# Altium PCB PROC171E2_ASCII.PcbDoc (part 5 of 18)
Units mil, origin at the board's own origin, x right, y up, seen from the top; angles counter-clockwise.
Board outline 7700 x 2300 mil, 6 copper layers (Top Layer, GND 1, SIG 1, SIG 2, GND 2, Bottom Layer), stack 61.062 mil thick; 938 components, 688 nets, 11933 pads, 1723 vias.
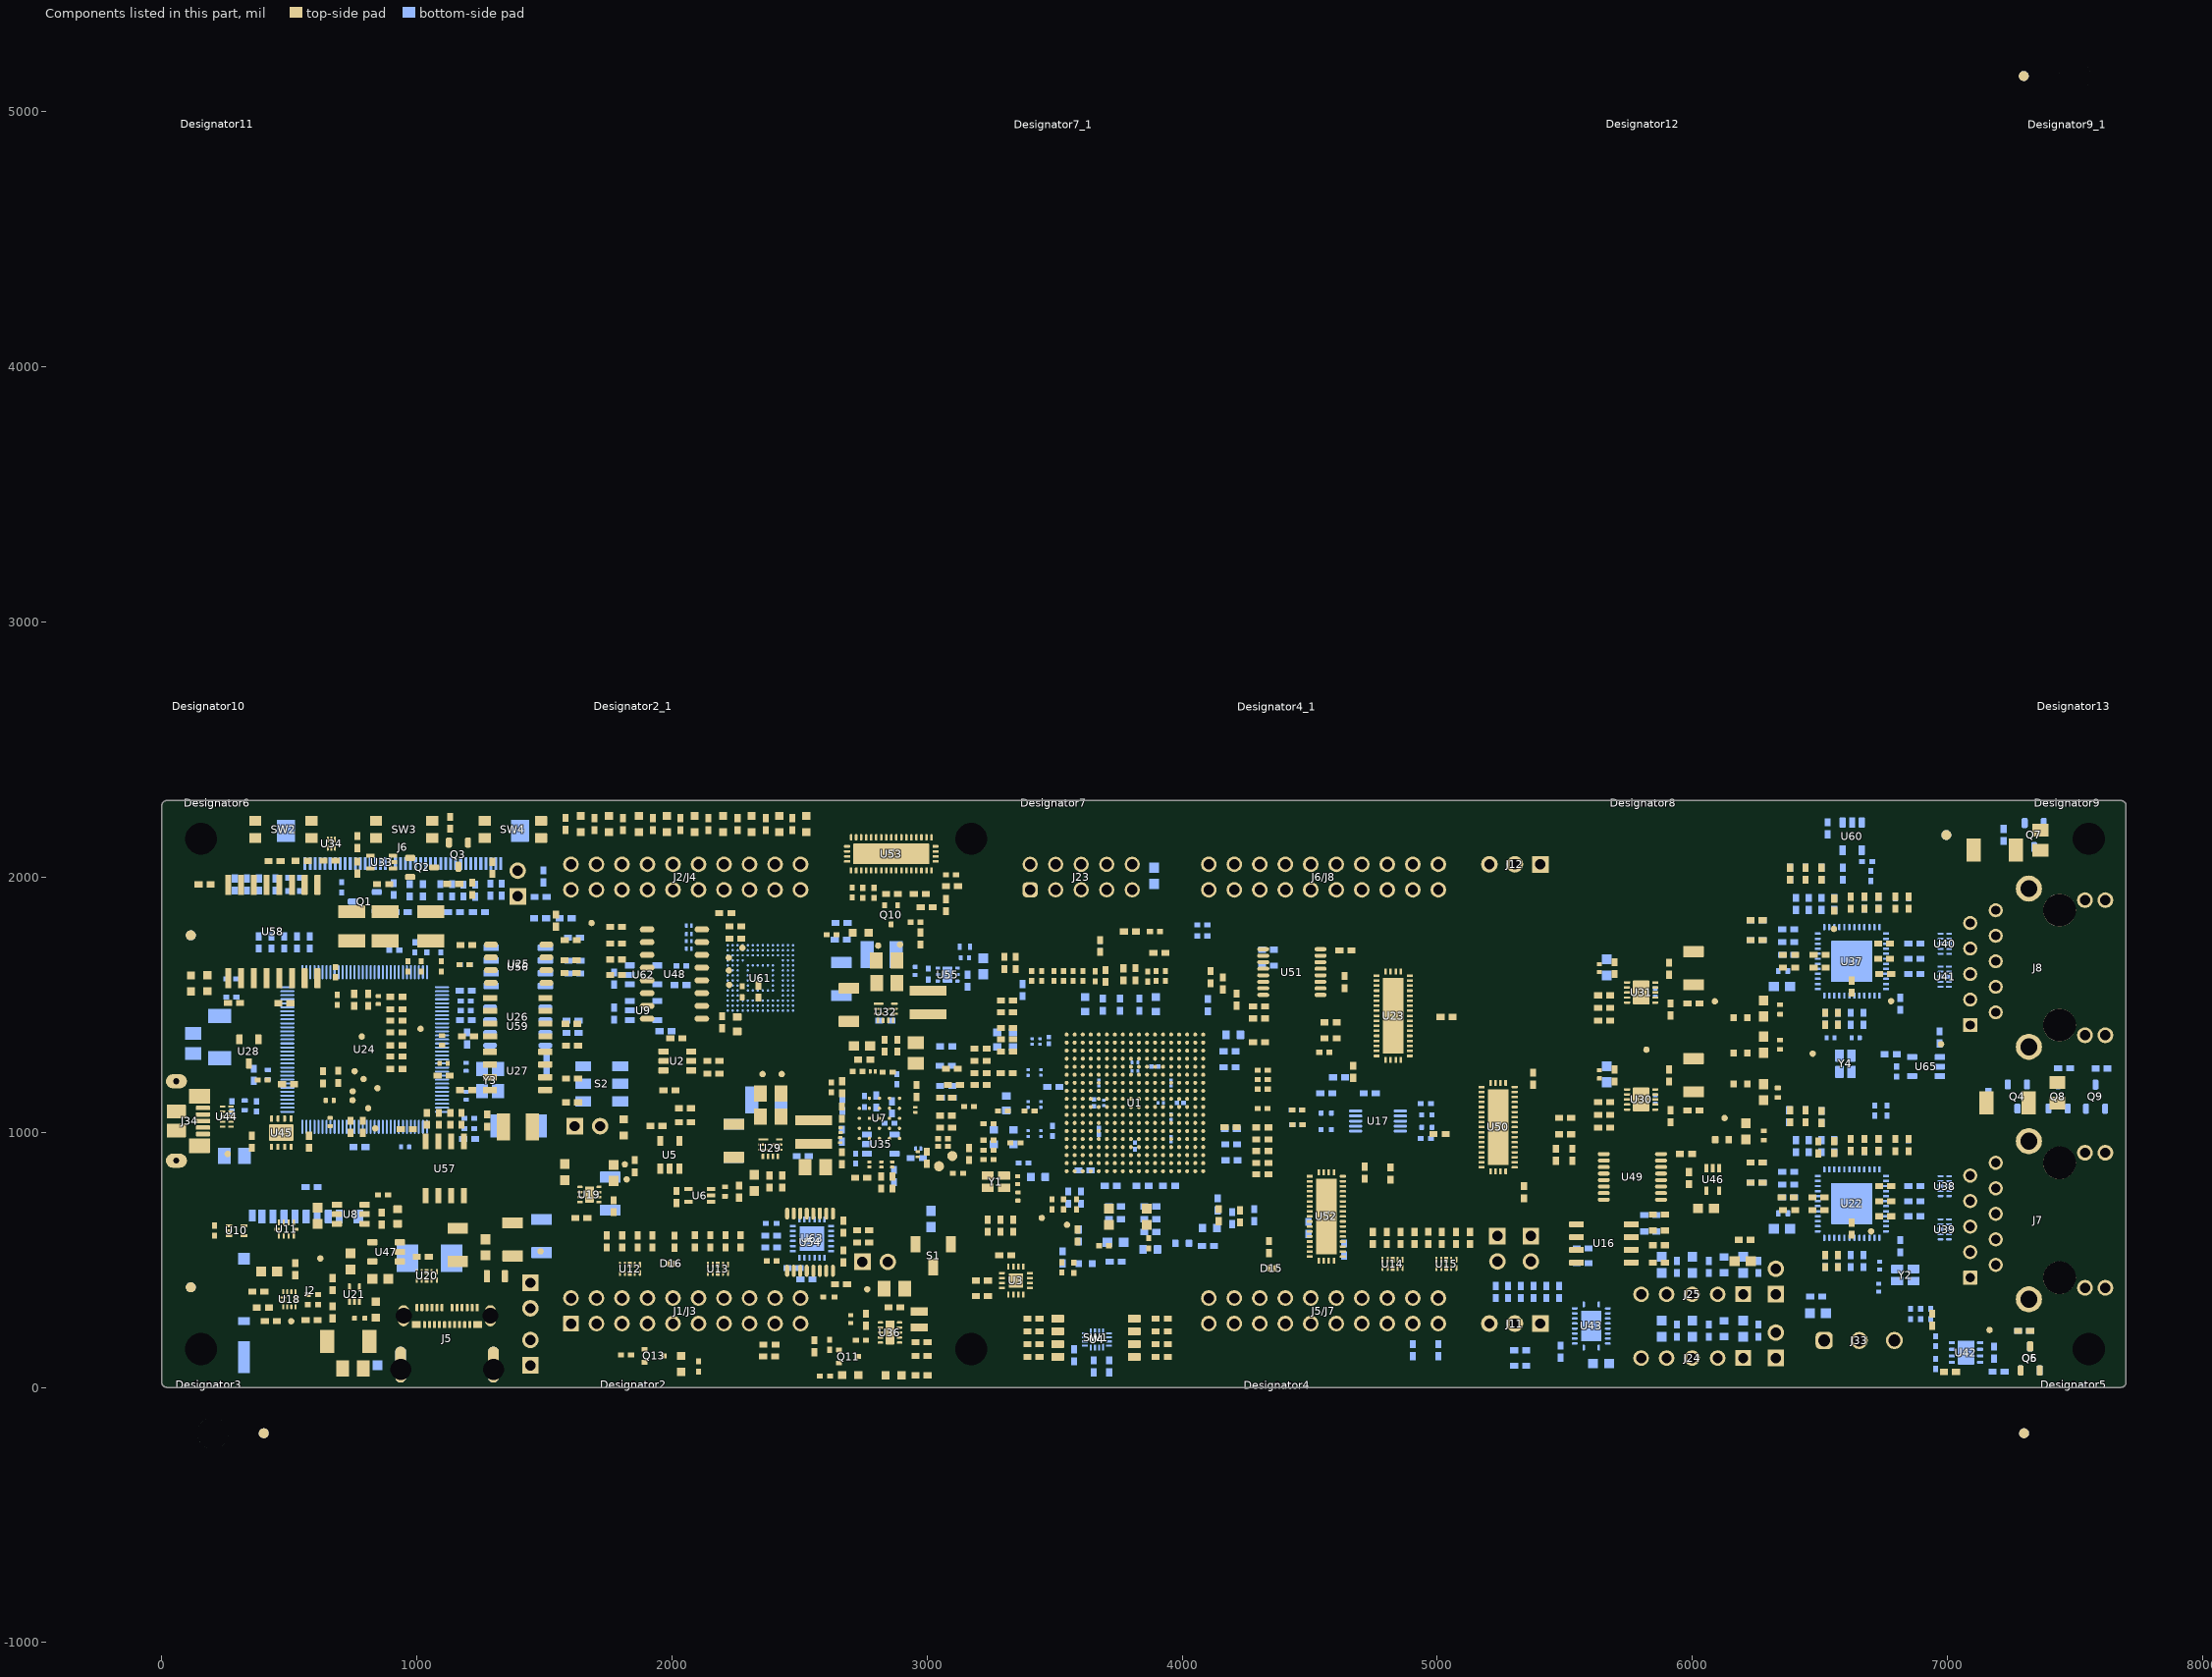
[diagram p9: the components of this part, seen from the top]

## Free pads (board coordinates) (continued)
  round 1 on Mech23: 1(3064.17,-75) 1(3064.17,-75) 1(3064.17,-55) 1(3064.17,-55) 1(3068.17,-71) 1(3068.17,-71) 1(3068.17,-59) 1(3068.17,-59) 1(3069.17,-65) 1(3069.17,-65) 1(3071.17,-65) 1(3071.17,-65) 1(3074.17,-70) 1(3074.17,-70) 1(3074.17,-68) 1(3074.17,-68) 1(3074.17,-62) 1(3074.17,-62) 1(3074.17,-60) 1(3074.17,-60) 1(3074.57,241.61) 1(3074.57,241.61) 1(3074.57,246.61) 1(3074.57,246.61) 1(3074.57,256.61) 1(3074.57,256.61) 1(3074.57,261.61) 1(3074.57,261.61) 1(3074.57,546.73) 1(3074.57,546.73) 1(3074.57,551.73) 1(3074.57,551.73) 1(3074.57,561.73) 1(3074.57,561.73) 1(3074.57,566.73) 1(3074.57,566.73) 1(3077.17,-65) 1(3077.17,-65) 1(3079.17,-65) 1(3079.17,-65) 1(3079.57,241.61) 1(3079.57,241.61) 1(3079.57,251.61) 1(3079.57,251.61) 1(3079.57,261.61) 1(3079.57,261.61) 1(3079.57,546.73) 1(3079.57,546.73) 1(3079.57,556.73) 1(3079.57,556.73) 1(3079.57,566.73) 1(3079.57,566.73) 1(3080.17,-71) 1(3080.17,-71) 1(3080.17,-59) 1(3080.17,-59) 1(3084.17,-75) 1(3084.17,-75) 1(3084.17,-55) 1(3084.17,-55) 1(3084.57,246.61) 1(3084.57,246.61) 1(3084.57,256.61) 1(3084.57,256.61) 1(3084.57,551.73) 1(3084.57,551.73) 1(3084.57,561.73) 1(3084.57,561.73) 1(3089.57,241.61) 1(3089.57,241.61) 1(3089.57,251.61) 1(3089.57,251.61) 1(3089.57,261.61) 1(3089.57,261.61) 1(3089.57,546.73) 1(3089.57,546.73) 1(3089.57,556.73) 1(3089.57,556.73) 1(3089.57,566.73) 1(3089.57,566.73) 1(3094.17,840) 1(3094.17,840) 1(3094.17,860) 1(3094.17,860) 1(3094.17,940) 1(3094.17,940) 1(3094.17,960) 1(3094.17,960) 1(3094.17,1040) 1(3094.17,1040) 1(3094.17,1060) 1(3094.17,1060) 1(3094.57,241.61) 1(3094.57,241.61) 1(3094.57,246.61) 1(3094.57,246.61) 1(3094.57,256.61) 1(3094.57,256.61) 1(3094.57,261.61) 1(3094.57,261.61) 1(3094.57,546.73) 1(3094.57,546.73) 1(3094.57,551.73) 1(3094.57,551.73) 1(3094.57,561.73) 1(3094.57,561.73) 1(3094.57,566.73) 1(3094.57,566.73) 1(3099.17,850) 1(3099.17,850) 1(3099.17,950) 1(3099.17,950) 1(3099.17,1050) 1(3099.17,1050) 1(3104.17,845) 1(3104.17,845) 1(3104.17,855) 1(3104.17,855) 1(3104.17,945) 1(3104.17,945) 1(3104.17,955) 1(3104.17,955) 1(3104.17,1045) 1(3104.17,1045) 1(3104.17,1055) 1(3104.17,1055) 1(3109.17,850) 1(3109.17,850) 1(3109.17,950) 1(3109.17,950) 1(3109.17,1050) 1(3109.17,1050) 1(3114.17,840) 1(3114.17,840) 1(3114.17,860) 1(3114.17,860) 1(3114.17,940) 1(3114.17,940) 1(3114.17,960) 1(3114.17,960) 1(3114.17,1040) 1(3114.17,1040) 1(3114.17,1060) 1(3114.17,1060) 1(3116.17,-123) 1(3116.17,-123) 1(3116.17,-103) 1(3116.17,-103) 1(3119.8,2072.52) 1(3119.8,2072.52) 1(3119.8,2082.52) 1(3119.8,2082.52) 1(3119.8,2151.26) 1(3119.8,2151.26) 1(3119.8,2161.26) 1(3119.8,2161.26) 1(3119.8,2230) 1(3119.8,2230) 1(3119.8,2240) 1(3119.8,2240) 1(3119.8,2308.74) 1(3119.8,2308.74) 1(3119.8,2318.74) 1(3119.8,2318.74) 1(3119.8,2387.48) 1(3119.8,2387.48) 1(3119.8,2397.48) 1(3119.8,2397.48) 1(3120.17,-119) 1(3120.17,-119) 1(3120.17,-107) 1(3120.17,-107) 1(3121.17,-113) 1(3121.17,-113) 1(3123.17,-113) 1(3123.17,-113) 1(3123.8,2074.52) 1(3123.8,2074.52) 1(3123.8,2080.52) 1(3123.8,2080.52) 1(3123.8,2153.26) 1(3123.8,2153.26) 1(3123.8,2159.26) 1(3123.8,2159.26) 1(3123.8,2232) 1(3123.8,2232) 1(3123.8,2238) 1(3123.8,2238) 1(3123.8,2310.74) 1(3123.8,2310.74) 1(3123.8,2316.74) 1(3123.8,2316.74) 1(3123.8,2389.48) 1(3123.8,2389.48) 1(3123.8,2395.48) 1(3123.8,2395.48) 1(3124.8,2067.52) 1(3124.8,2067.52) 1(3124.8,2072.52) 1(3124.8,2072.52) 1(3124.8,2082.52) 1(3124.8,2082.52) 1(3124.8,2087.52) 1(3124.8,2087.52) 1(3124.8,2146.26) 1(3124.8,2146.26) 1(3124.8,2151.26) 1(3124.8,2151.26) 1(3124.8,2161.26) 1(3124.8,2161.26) 1(3124.8,2166.26) 1(3124.8,2166.26) 1(3124.8,2225) 1(3124.8,2225) 1(3124.8,2230) 1(3124.8,2230) 1(3124.8,2240) 1(3124.8,2240) 1(3124.8,2245) 1(3124.8,2245) 1(3124.8,2303.74) 1(3124.8,2303.74) 1(3124.8,2308.74) 1(3124.8,2308.74) 1(3124.8,2318.74) 1(3124.8,2318.74) 1(3124.8,2323.74) 1(3124.8,2323.74) 1(3124.8,2382.48) 1(3124.8,2382.48) 1(3124.8,2387.48) 1(3124.8,2387.48) 1(3124.8,2397.48) 1(3124.8,2397.48) 1(3124.8,2402.48) 1(3124.8,2402.48) 1(3126.17,-118) 1(3126.17,-118) 1(3126.17,-116) 1(3126.17,-116) 1(3126.17,-110) 1(3126.17,-110) 1(3126.17,-108) 1(3126.17,-108) 1(3126.8,2071.52) 1(3126.8,2071.52) 1(3126.8,2074.52) 1(3126.8,2074.52) 1(3126.8,2080.52) 1(3126.8,2080.52) 1(3126.8,2083.52) 1(3126.8,2083.52) 1(3126.8,2150.26) 1(3126.8,2150.26) 1(3126.8,2153.26) 1(3126.8,2153.26) 1(3126.8,2159.26) 1(3126.8,2159.26) 1(3126.8,2162.26) 1(3126.8,2162.26) 1(3126.8,2229) 1(3126.8,2229) 1(3126.8,2232) 1(3126.8,2232) 1(3126.8,2238) 1(3126.8,2238) 1(3126.8,2241) 1(3126.8,2241) 1(3126.8,2307.74) 1(3126.8,2307.74) 1(3126.8,2310.74) 1(3126.8,2310.74) 1(3126.8,2316.74) 1(3126.8,2316.74) 1(3126.8,2319.74) 1(3126.8,2319.74) 1(3126.8,2386.48) 1(3126.8,2386.48) 1(3126.8,2389.48) 1(3126.8,2389.48) 1(3126.8,2395.48) 1(3126.8,2395.48) 1(3126.8,2398.48) 1(3126.8,2398.48) 1(3129.17,-113) 1(3129.17,-113) 1(3131.17,-113) 1(3131.17,-113) 1(3132.17,-119) 1(3132.17,-119) 1(3132.17,-107) 1(3132.17,-107) 1(3132.8,2071.52) 1(3132.8,2071.52) 1(3132.8,2074.52) 1(3132.8,2074.52) 1(3132.8,2080.52) 1(3132.8,2080.52) 1(3132.8,2083.52) 1(3132.8,2083.52) 1(3132.8,2150.26) 1(3132.8,2150.26) 1(3132.8,2153.26) 1(3132.8,2153.26) 1(3132.8,2159.26) 1(3132.8,2159.26) 1(3132.8,2162.26) 1(3132.8,2162.26) 1(3132.8,2229) 1(3132.8,2229) 1(3132.8,2232) 1(3132.8,2232) 1(3132.8,2238) 1(3132.8,2238) 1(3132.8,2241) 1(3132.8,2241) 1(3132.8,2307.74) 1(3132.8,2307.74) 1(3132.8,2310.74) 1(3132.8,2310.74) 1(3132.8,2316.74) 1(3132.8,2316.74) 1(3132.8,2319.74) 1(3132.8,2319.74) 1(3132.8,2386.48) 1(3132.8,2386.48) 1(3132.8,2389.48) 1(3132.8,2389.48) 1(3132.8,2395.48) 1(3132.8,2395.48) 1(3132.8,2398.48) 1(3132.8,2398.48) 1(3134.8,2067.52) 1(3134.8,2067.52) 1(3134.8,2072.52) 1(3134.8,2072.52) 1(3134.8,2082.52) 1(3134.8,2082.52) 1(3134.8,2087.52) 1(3134.8,2087.52) 1(3134.8,2146.26) 1(3134.8,2146.26) 1(3134.8,2151.26) 1(3134.8,2151.26) 1(3134.8,2161.26) 1(3134.8,2161.26) 1(3134.8,2166.26) 1(3134.8,2166.26) 1(3134.8,2225) 1(3134.8,2225) 1(3134.8,2230) 1(3134.8,2230) 1(3134.8,2240) 1(3134.8,2240) 1(3134.8,2245) 1(3134.8,2245) 1(3134.8,2303.74) 1(3134.8,2303.74) 1(3134.8,2308.74) 1(3134.8,2308.74) 1(3134.8,2318.74) 1(3134.8,2318.74) 1(3134.8,2323.74) 1(3134.8,2323.74) 1(3134.8,2382.48) 1(3134.8,2382.48) 1(3134.8,2387.48) 1(3134.8,2387.48) 1(3134.8,2397.48) 1(3134.8,2397.48) 1(3134.8,2402.48) 1(3134.8,2402.48) 1(3135.8,2074.52) 1(3135.8,2074.52) 1(3135.8,2080.52) 1(3135.8,2080.52) 1(3135.8,2153.26) 1(3135.8,2153.26) 1(3135.8,2159.26) 1(3135.8,2159.26) 1(3135.8,2232) 1(3135.8,2232) 1(3135.8,2238) 1(3135.8,2238) 1(3135.8,2310.74) 1(3135.8,2310.74) 1(3135.8,2316.74) 1(3135.8,2316.74) 1(3135.8,2389.48) 1(3135.8,2389.48) 1(3135.8,2395.48) 1(3135.8,2395.48) 1(3136.17,-123) 1(3136.17,-123) 1(3136.17,-103) 1(3136.17,-103) 1(3138.95,1545) 1(3138.95,1545) 1(3138.95,1565) 1(3138.95,1565) 1(3139.17,1680.75) 1(3139.17,1680.75) 1(3139.17,1700.75) 1(3139.17,1700.75) 1(3139.17,1879.17) 1(3139.17,1879.17) 1(3139.17,1899.17) 1(3139.17,1899.17) 1(3139.8,2072.52) 1(3139.8,2072.52) 1(3139.8,2082.52) 1(3139.8,2082.52) 1(3139.8,2151.26) 1(3139.8,2151.26) 1(3139.8,2161.26) 1(3139.8,2161.26) 1(3139.8,2230) 1(3139.8,2230) 1(3139.8,2240) 1(3139.8,2240) 1(3139.8,2308.74) 1(3139.8,2308.74) 1(3139.8,2318.74) 1(3139.8,2318.74) 1(3139.8,2387.48) 1(3139.8,2387.48) 1(3139.8,2397.48) 1(3139.8,2397.48) 1(3142.22,1190) 1(3142.22,1190) 1(3142.22,1210) 1(3142.22,1210) 1(3142.95,1549) 1(3142.95,1549) 1(3142.95,1561) 1(3142.95,1561) 1(3143.17,1684.75) 1(3143.17,1684.75) 1(3143.17,1696.75) 1(3143.17,1696.75) 1(3143.17,1883.17) 1(3143.17,1883.17) 1(3143.17,1895.17) 1(3143.17,1895.17) 1(3143.95,1555) 1(3143.95,1555) 1(3144.17,1690.75) 1(3144.17,1690.75) 1(3144.17,1889.17) 1(3144.17,1889.17) 1(3145.95,1555) 1(3145.95,1555) 1(3146.17,1690.75) 1(3146.17,1690.75) 1(3146.17,1889.17) 1(3146.17,1889.17) 1(3146.22,1194) 1(3146.22,1194) 1(3146.22,1206) 1(3146.22,1206) 1(3147.22,1200) 1(3147.22,1200) 1(3148.95,1550) 1(3148.95,1550) 1(3148.95,1552) 1(3148.95,1552) 1(3148.95,1558) 1(3148.95,1558) 1(3148.95,1560) 1(3148.95,1560) 1(3149.17,1685.75) 1(3149.17,1685.75) 1(3149.17,1687.75) 1(3149.17,1687.75) 1(3149.17,1693.75) 1(3149.17,1693.75) 1(3149.17,1695.75) 1(3149.17,1695.75) 1(3149.17,1884.17) 1(3149.17,1884.17) 1(3149.17,1886.17) 1(3149.17,1886.17) 1(3149.17,1892.17) 1(3149.17,1892.17) 1(3149.17,1894.17) 1(3149.17,1894.17) 1(3149.22,1200) 1(3149.22,1200) 1(3151.95,1555) 1(3151.95,1555) 1(3152.17,1690.75) 1(3152.17,1690.75) 1(3152.17,1889.17) 1(3152.17,1889.17) 1(3152.22,631.96) 1(3152.22,635.96) 1(3152.22,647.96) 1(3152.22,651.96) 1(3152.22,1195) 1(3152.22,1195) 1(3152.22,1197) 1(3152.22,1197) 1(3152.22,1203) 1(3152.22,1203) 1(3152.22,1205) 1(3152.22,1205) 1(3153.95,1555) 1(3153.95,1555) 1(3154.17,1690.75) 1(3154.17,1690.75) 1(3154.17,1889.17) 1(3154.17,1889.17) 1(3154.95,1549) 1(3154.95,1549) 1(3154.95,1561) 1(3154.95,1561) 1(3155.17,1684.75) 1(3155.17,1684.75) 1(3155.17,1696.75) 1(3155.17,1696.75) 1(3155.17,1883.17) 1(3155.17,1883.17) 1(3155.17,1895.17) 1(3155.17,1895.17) 1(3155.22,1200) 1(3155.22,1200) 1(3157.22,1200) 1(3157.22,1200) 1(3158.22,1194) 1(3158.22,1194) 1(3158.22,1206) 1(3158.22,1206) 1(3158.36,1240) 1(3158.36,1240) 1(3158.36,1260) 1(3158.36,1260) 1(3158.36,1440) 1(3158.36,1440) 1(3158.36,1460) 1(3158.36,1460) 1(3158.95,1545) 1(3158.95,1545) 1(3158.95,1565) 1(3158.95,1565) 1(3159.17,1680.75) 1(3159.17,1680.75) 1(3159.17,1700.75) 1(3159.17,1700.75) 1(3159.17,1879.17) 1(3159.17,1879.17) 1(3159.17,1899.17) 1(3159.17,1899.17) 1(3162.22,1190) 1(3162.22,1190) 1(3162.22,1210) 1(3162.22,1210) 1(3162.36,1244) 1(3162.36,1244) 1(3162.36,1256) 1(3162.36,1256) 1(3162.36,1444) 1(3162.36,1444) 1(3162.36,1456) 1(3162.36,1456) 1(3163.36,1250) 1(3163.36,1250) 1(3163.36,1450) 1(3163.36,1450) 1(3165.36,1250) 1(3165.36,1250) 1(3165.36,1450) 1(3165.36,1450) 1(3168.36,1245) 1(3168.36,1245) 1(3168.36,1247) 1(3168.36,1247) 1(3168.36,1253) 1(3168.36,1253) 1(3168.36,1255) 1(3168.36,1255) 1(3168.36,1445) 1(3168.36,1445) 1(3168.36,1447) 1(3168.36,1447) 1(3168.36,1453) 1(3168.36,1453) 1(3168.36,1455) 1(3168.36,1455) 1(3171.36,1250) 1(3171.36,1250) 1(3171.36,1450) 1(3171.36,1450) 1(3173.36,1250) 1(3173.36,1250) 1(3173.36,1450) 1(3173.36,1450) 1(3174.17,-75) 1(3174.17,-75) 1(3174.17,-55) 1(3174.17,-55) 1(3174.36,1244) 1(3174.36,1244) 1(3174.36,1256) 1(3174.36,1256) 1(3174.36,1444) 1(3174.36,1444) 1(3174.36,1456) 1(3174.36,1456) 1(3178.17,-71) 1(3178.17,-71) 1(3178.17,-59) 1(3178.17,-59) 1(3178.36,1240) 1(3178.36,1240) 1(3178.36,1260) 1(3178.36,1260) 1(3178.36,1440) 1(3178.36,1440) 1(3178.36,1460) 1(3178.36,1460) 1(3179.17,-65) 1(3179.17,-65) 1(3180.86,300.74) 1(3180.86,300.74) 1(3180.86,310.74) 1(3180.86,310.74) 1(3180.86,497.59) 1(3180.86,497.59) 1(3180.86,507.59) 1(3180.86,507.59) 1(3181.17,-65) 1(3181.17,-65) 1(3184.17,-70) 1(3184.17,-70) 1(3184.17,-68) 1(3184.17,-68) 1(3184.17,-62) 1(3184.17,-62) 1(3184.17,-60) 1(3184.17,-60) 1(3185.86,295.74) 1(3185.86,295.74) 1(3185.86,300.74) 1(3185.86,300.74) 1(3185.86,310.74) 1(3185.86,310.74) 1(3185.86,315.74) 1(3185.86,315.74) 1(3185.86,492.59) 1(3185.86,492.59) 1(3185.86,497.59) 1(3185.86,497.59) 1(3185.86,507.59) 1(3185.86,507.59) 1(3185.86,512.59) 1(3185.86,512.59) 1(3187.17,-65) 1(3187.17,-65) 1(3189.17,-65) 1(3189.17,-65) 1(3190.17,-71) 1(3190.17,-71) 1(3190.17,-59) 1(3190.17,-59) 1(3194.17,-75) 1(3194.17,-75) 1(3194.17,-55) 1(3194.17,-55) 1(3195.86,295.74) 1(3195.86,295.74) 1(3195.86,300.74) 1(3195.86,300.74) 1(3195.86,310.74) 1(3195.86,310.74) 1(3195.86,315.74) 1(3195.86,315.74) 1(3195.86,492.59) 1(3195.86,492.59) 1(3195.86,497.59) 1(3195.86,497.59) 1(3195.86,507.59) 1(3195.86,507.59) 1(3195.86,512.59) 1(3195.86,512.59) 1(3198.54,2072.52) 1(3198.54,2072.52) 1(3198.54,2082.52) 1(3198.54,2082.52) 1(3198.54,2151.26) 1(3198.54,2151.26) 1(3198.54,2161.26) 1(3198.54,2161.26) 1(3198.54,2230) 1(3198.54,2230) 1(3198.54,2240) 1(3198.54,2240) 1(3198.54,2308.74) 1(3198.54,2308.74) 1(3198.54,2318.74) 1(3198.54,2318.74) 1(3198.54,2387.48) 1(3198.54,2387.48) 1(3198.54,2397.48) 1(3198.54,2397.48) 1(3200.86,300.74) 1(3200.86,300.74) 1(3200.86,310.74) 1(3200.86,310.74) 1(3200.86,497.59) 1(3200.86,497.59) 1(3200.86,507.59) 1(3200.86,507.59) 1(3202.54,2074.52) 1(3202.54,2074.52) 1(3202.54,2080.52) 1(3202.54,2080.52) 1(3202.54,2153.26) 1(3202.54,2153.26) 1(3202.54,2159.26) 1(3202.54,2159.26) 1(3202.54,2232) 1(3202.54,2232) 1(3202.54,2238) 1(3202.54,2238) 1(3202.54,2310.74) 1(3202.54,2310.74) 1(3202.54,2316.74) 1(3202.54,2316.74) 1(3202.54,2389.48) 1(3202.54,2389.48) 1(3202.54,2395.48) 1(3202.54,2395.48) 1(3203.54,2067.52) 1(3203.54,2067.52) 1(3203.54,2072.52) 1(3203.54,2072.52) 1(3203.54,2082.52) 1(3203.54,2082.52) 1(3203.54,2087.52) 1(3203.54,2087.52) 1(3203.54,2146.26) 1(3203.54,2146.26) 1(3203.54,2151.26) 1(3203.54,2151.26) 1(3203.54,2161.26) 1(3203.54,2161.26) 1(3203.54,2166.26) 1(3203.54,2166.26) 1(3203.54,2225) 1(3203.54,2225) 1(3203.54,2230) 1(3203.54,2230) 1(3203.54,2240) 1(3203.54,2240) 1(3203.54,2245) 1(3203.54,2245) 1(3203.54,2303.74) 1(3203.54,2303.74) 1(3203.54,2308.74) 1(3203.54,2308.74) 1(3203.54,2318.74) 1(3203.54,2318.74) 1(3203.54,2323.74) 1(3203.54,2323.74) 1(3203.54,2382.48) 1(3203.54,2382.48) 1(3203.54,2387.48) 1(3203.54,2387.48) 1(3203.54,2397.48) 1(3203.54,2397.48) 1(3203.54,2402.48) 1(3203.54,2402.48) 1(3205.54,2071.52) 1(3205.54,2071.52) 1(3205.54,2074.52) 1(3205.54,2074.52) 1(3205.54,2080.52) 1(3205.54,2080.52) 1(3205.54,2083.52) 1(3205.54,2083.52) 1(3205.54,2150.26) 1(3205.54,2150.26) 1(3205.54,2153.26) 1(3205.54,2153.26) 1(3205.54,2159.26) 1(3205.54,2159.26) 1(3205.54,2162.26) 1(3205.54,2162.26) 1(3205.54,2229) 1(3205.54,2229) 1(3205.54,2232) 1(3205.54,2232) 1(3205.54,2238) 1(3205.54,2238) 1(3205.54,2241) 1(3205.54,2241) 1(3205.54,2307.74) 1(3205.54,2307.74) 1(3205.54,2310.74) 1(3205.54,2310.74) 1(3205.54,2316.74) 1(3205.54,2316.74) 1(3205.54,2319.74) 1(3205.54,2319.74) 1(3205.54,2386.48) 1(3205.54,2386.48) 1(3205.54,2389.48) 1(3205.54,2389.48) 1(3205.54,2395.48) 1(3205.54,2395.48) 1(3205.54,2398.48) 1(3205.54,2398.48) 1(3211.54,2071.52) 1(3211.54,2071.52) 1(3211.54,2074.52) 1(3211.54,2074.52) 1(3211.54,2080.52) 1(3211.54,2080.52) 1(3211.54,2083.52) 1(3211.54,2083.52) 1(3211.54,2150.26) 1(3211.54,2150.26) 1(3211.54,2153.26) 1(3211.54,2153.26) 1(3211.54,2159.26) 1(3211.54,2159.26) 1(3211.54,2162.26) 1(3211.54,2162.26) 1(3211.54,2229) 1(3211.54,2229) 1(3211.54,2232) 1(3211.54,2232) 1(3211.54,2238) 1(3211.54,2238) 1(3211.54,2241) 1(3211.54,2241) 1(3211.54,2307.74) 1(3211.54,2307.74) 1(3211.54,2310.74) 1(3211.54,2310.74) 1(3211.54,2316.74) 1(3211.54,2316.74) 1(3211.54,2319.74) 1(3211.54,2319.74) 1(3211.54,2386.48) 1(3211.54,2386.48) 1(3211.54,2389.48) 1(3211.54,2389.48) 1(3211.54,2395.48) 1(3211.54,2395.48) 1(3211.54,2398.48) 1(3211.54,2398.48) 1(3213.54,2067.52) 1(3213.54,2067.52) 1(3213.54,2072.52) 1(3213.54,2072.52) 1(3213.54,2082.52) 1(3213.54,2082.52) 1(3213.54,2087.52) 1(3213.54,2087.52) 1(3213.54,2146.26) 1(3213.54,2146.26) 1(3213.54,2151.26) 1(3213.54,2151.26) 1(3213.54,2161.26) 1(3213.54,2161.26) 1(3213.54,2166.26) 1(3213.54,2166.26) 1(3213.54,2225) 1(3213.54,2225) 1(3213.54,2230) 1(3213.54,2230) 1(3213.54,2240) 1(3213.54,2240) 1(3213.54,2245) 1(3213.54,2245) 1(3213.54,2303.74) 1(3213.54,2303.74) 1(3213.54,2308.74) 1(3213.54,2308.74) 1(3213.54,2318.74) 1(3213.54,2318.74) 1(3213.54,2323.74) 1(3213.54,2323.74) 1(3213.54,2382.48) 1(3213.54,2382.48) 1(3213.54,2387.48) 1(3213.54,2387.48) 1(3213.54,2397.48) 1(3213.54,2397.48) 1(3213.54,2402.48) 1(3213.54,2402.48) 1(3214.54,2074.52) 1(3214.54,2074.52) 1(3214.54,2080.52) 1(3214.54,2080.52) 1(3214.54,2153.26) 1(3214.54,2153.26) 1(3214.54,2159.26) 1(3214.54,2159.26) 1(3214.54,2232) 1(3214.54,2232) 1(3214.54,2238) 1(3214.54,2238) 1(3214.54,2310.74) 1(3214.54,2310.74) 1(3214.54,2316.74) 1(3214.54,2316.74) 1(3214.54,2389.48) 1(3214.54,2389.48) 1(3214.54,2395.48) 1(3214.54,2395.48) 1(3218.54,2072.52) 1(3218.54,2072.52) 1(3218.54,2082.52) 1(3218.54,2082.52) 1(3218.54,2151.26) 1(3218.54,2151.26) 1(3218.54,2161.26) 1(3218.54,2161.26) 1(3218.54,2230) 1(3218.54,2230) 1(3218.54,2240) 1(3218.54,2240) 1(3218.54,2308.74) 1(3218.54,2308.74) 1(3218.54,2318.74) 1(3218.54,2318.74) 1(3218.54,2387.48) 1(3218.54,2387.48) 1(3218.54,2397.48) 1(3218.54,2397.48) 1(3219.17,1680.75) 1(3219.17,1680.75) 1(3219.17,1700.75) 1(3219.17,1700.75) 1(3223.17,1684.75) 1(3223.17,1684.75) 1(3223.17,1696.75) 1(3223.17,1696.75) 1(3224.17,257.51) 1(3224.17,257.51) 1(3224.17,550.82) 1(3224.17,550.82) 1(3224.17,1690.75) 1(3224.17,1690.75) 1(3224.17,1877.68) 1(3224.17,1877.68) 1(3224.17,1897.68) 1(3224.17,1897.68) 1(3226.17,1690.75) 1(3226.17,1690.75) 1(3228.17,1881.68) 1(3228.17,1881.68) 1(3228.17,1893.68) 1(3228.17,1893.68) 1(3229.17,1685.75) 1(3229.17,1685.75) 1(3229.17,1687.75) 1(3229.17,1687.75) 1(3229.17,1693.75) 1(3229.17,1693.75) 1(3229.17,1695.75) 1(3229.17,1695.75) 1(3229.17,1887.68) 1(3229.17,1887.68) 1(3231.17,1887.68) 1(3231.17,1887.68) 1(3232.17,1690.75) 1(3232.17,1690.75) 1(3234.17,247.51) 1(3234.17,247.51) 1(3234.17,267.51) 1(3234.17,267.51) 1(3234.17,540.82) 1(3234.17,540.82) 1(3234.17,560.82) 1(3234.17,560.82) 1(3234.17,1690.75) 1(3234.17,1690.75) 1(3234.17,1882.68) 1(3234.17,1882.68) 1(3234.17,1884.68) 1(3234.17,1884.68) 1(3234.17,1890.68) 1(3234.17,1890.68) 1(3234.17,1892.68) 1(3234.17,1892.68) 1(3235.17,1684.75) 1(3235.17,1684.75) 1(3235.17,1696.75) 1(3235.17,1696.75) 1(3237.17,1887.68) 1(3237.17,1887.68) 1(3239.17,1680.75) 1(3239.17,1680.75) 1(3239.17,1700.75) 1(3239.17,1700.75) 1(3239.17,1887.68) 1(3239.17,1887.68) 1(3240.17,1881.68) 1(3240.17,1881.68) 1(3240.17,1893.68) 1(3240.17,1893.68) 1(3244.17,257.51) 1(3244.17,257.51) 1(3244.17,550.82) 1(3244.17,550.82) 1(3244.17,1877.68) 1(3244.17,1877.68) 1(3244.17,1897.68) 1(3244.17,1897.68) 1(3274.17,342.99) 1(3274.17,342.99) 1(3274.17,362.99) 1(3274.17,362.99) 1(3278.17,346.99) 1(3278.17,346.99) 1(3278.17,358.99) 1(3278.17,358.99) 1(3279.17,352.99) 1(3279.17,352.99) 1(3281.17,352.99) 1(3281.17,352.99) 1(3284.17,347.99) 1(3284.17,347.99) 1(3284.17,349.99) 1(3284.17,349.99) 1(3284.17,355.99) 1(3284.17,355.99) 1(3284.17,357.99) 1(3284.17,357.99) 1(3287.17,352.99) 1(3287.17,352.99) 1(3289.17,352.99) 1(3289.17,352.99) 1(3290.17,346.99) 1(3290.17,346.99) 1(3290.17,358.99) 1(3290.17,358.99) 1(3294.17,342.99) 1(3294.17,342.99) 1(3294.17,362.99) 1(3294.17,362.99) 1(3312.16,2447) 1(3312.16,2447) 1(3312.16,2467) 1(3312.16,2467) 1(3313.49,180) 1(3313.49,180) 1(3313.49,200) 1(3313.49,200) 1(3316.16,2451) 1(3316.16,2451) 1(3316.16,2463) 1(3316.16,2463) 1(3317.16,2457) 1(3317.16,2457) 1(3317.49,184) 1(3317.49,184) 1(3317.49,196) 1(3317.49,196) 1(3318.49,190) 1(3318.49,190) 1(3319.16,2457) 1(3319.16,2457) 1(3320.49,190) 1(3320.49,190) 1(3322.16,2452) 1(3322.16,2452) 1(3322.16,2454) 1(3322.16,2454) 1(3322.16,2460) 1(3322.16,2460) 1(3322.16,2462) 1(3322.16,2462) 1(3323.49,185) 1(3323.49,185) 1(3323.49,187) 1(3323.49,187) 1(3323.49,193) 1(3323.49,193) 1(3323.49,195) 1(3323.49,195) 1(3325.16,2457) 1(3325.16,2457) 1(3326.49,190) 1(3326.49,190) 1(3327.16,2457) 1(3327.16,2457) 1(3328.16,2451) 1(3328.16,2451) 1(3328.16,2463) 1(3328.16,2463) 1(3328.49,190) 1(3328.49,190) 1(3329.49,184) 1(3329.49,184) 1(3329.49,196) 1(3329.49,196) 1(3332.16,2447) 1(3332.16,2447) 1(3332.16,2467) 1(3332.16,2467) 1(3333.49,180) 1(3333.49,180) 1(3333.49,200) 1(3333.49,200) 1(3342.19,529.05) 1(3342.19,529.05) 1(3342.19,549.05) 1(3342.19,549.05) 1(3346.19,533.05) 1(3346.19,533.05) 1(3346.19,545.05) 1(3346.19,545.05) 1(3347.19,539.05) 1(3347.19,539.05) 1(3349.19,539.05) 1(3349.19,539.05) 1(3352.19,534.05) 1(3352.19,534.05) 1(3352.19,536.05) 1(3352.19,536.05) 1(3352.19,542.05) 1(3352.19,542.05) 1(3352.19,544.05) 1(3352.19,544.05) 1(3355.19,539.05) 1(3355.19,539.05) 1(3357.19,539.05) 1(3357.19,539.05) 1(3358.19,533.05) 1(3358.19,533.05) 1(3358.19,545.05) 1(3358.19,545.05) 1(3361.57,1673.5) 1(3361.57,1673.5) 1(3361.57,1693.5) 1(3361.57,1693.5) 1(3362.19,529.05) 1(3362.19,529.05) 1(3362.19,549.05) 1(3362.19,549.05) 1(3365.57,1677.5) 1(3365.57,1677.5) 1(3365.57,1689.5) 1(3365.57,1689.5) 1(3366.57,1683.5) 1(3366.57,1683.5) 1(3368.57,1683.5) 1(3368.57,1683.5) 1(3371.57,1678.5) 1(3371.57,1678.5) 1(3371.57,1680.5) 1(3371.57,1680.5) 1(3371.57,1686.5) 1(3371.57,1686.5) 1(3371.57,1688.5) 1(3371.57,1688.5) 1(3374.57,1683.5) 1(3374.57,1683.5) 1(3376.57,1683.5) 1(3376.57,1683.5) 1(3377.57,1677.5) 1(3377.57,1677.5) 1(3377.57,1689.5) 1(3377.57,1689.5) 1(3379.76,1440) 1(3379.76,1440) 1(3379.76,1460) 1(3379.76,1460) 1(3380.27,1240) 1(3380.27,1240) 1(3380.27,1260) 1(3380.27,1260) 1(3381.57,1673.5) 1(3381.57,1673.5) 1(3381.57,1693.5) 1(3381.57,1693.5) 1(3383.76,1444) 1(3383.76,1444) 1(3383.76,1456) 1(3383.76,1456) 1(3384.27,1244) 1(3384.27,1244) 1(3384.27,1256) 1(3384.27,1256) 1(3384.76,1450) 1(3384.76,1450) 1(3385.27,1250) 1(3385.27,1250) 1(3386.76,1450) 1(3386.76,1450) 1(3387.27,1250) 1(3387.27,1250) 1(3389.76,1445) 1(3389.76,1445) 1(3389.76,1447) 1(3389.76,1447) 1(3389.76,1453) 1(3389.76,1453) 1(3389.76,1455) 1(3389.76,1455) 1(3390.27,1245) 1(3390.27,1245) 1(3390.27,1247) 1(3390.27,1247) 1(3390.27,1253) 1(3390.27,1253) 1(3390.27,1255) 1(3390.27,1255) 1(3391.87,1118.74) 1(3391.87,1118.74) 1(3391.87,1138.74) 1(3391.87,1138.74) 1(3392.76,1450) 1(3392.76,1450) 1(3393.27,1250) 1(3393.27,1250) 1(3394.17,1940) 1(3394.17,1940) 1(3394.17,1960) 1(3394.17,1960) 1(3394.17,2040) 1(3394.17,2040) 1(3394.17,2060) 1(3394.17,2060) 1(3394.76,1450) 1(3394.76,1450) 1(3395.27,1250) 1(3395.27,1250) 1(3395.76,1444) 1(3395.76,1444) 1(3395.76,1456) 1(3395.76,1456) 1(3395.87,1122.74) 1(3395.87,1122.74) 1(3395.87,1134.74) 1(3395.87,1134.74) 1(3396.27,1244) 1(3396.27,1244) 1(3396.27,1256) 1(3396.27,1256) 1(3396.87,1128.74) 1(3396.87,1128.74) 1(3398.17,1944) 1(3398.17,1944) 1(3398.17,1956) 1(3398.17,1956) 1(3398.17,2044) 1(3398.17,2044) 1(3398.17,2056) 1(3398.17,2056) 1(3398.87,1128.74) 1(3398.87,1128.74) 1(3399.76,1440) 1(3399.76,1440) 1(3399.76,1460) 1(3399.76,1460) 1(3400.27,1240) 1(3400.27,1240) 1(3400.27,1260) 1(3400.27,1260) 1(3401.87,1123.74) 1(3401.87,1123.74) 1(3401.87,1125.74) 1(3401.87,1125.74) 1(3401.87,1131.74) 1(3401.87,1131.74) 1(3401.87,1133.74) 1(3401.87,1133.74) 1(3404.87,1128.74) 1(3404.87,1128.74) 1(3406.87,1128.74) 1(3406.87,1128.74) 1(3407.87,1122.74) 1(3407.87,1122.74) 1(3407.87,1134.74) 1(3407.87,1134.74) 1(3409.17,-79.79) 1(3409.17,-79.79) 1(3409.17,-59.79) 1(3409.17,-59.79) 1(3410.17,1944) 1(3410.17,1944) 1(3410.17,1956) 1(3410.17,1956) 1(3410.17,2044) 1(3410.17,2044) 1(3410.17,2056) 1(3410.17,2056) 1(3411.87,1118.74) 1(3411.87,1118.74) 1(3411.87,1138.74) 1(3411.87,1138.74) 1(3413.17,-75.79) 1(3413.17,-75.79) 1(3413.17,-63.79) 1(3413.17,-63.79) 1(3414.17,-69.79) 1(3414.17,-69.79) 1(3414.17,1940) 1(3414.17,1940) 1(3414.17,1960) 1(3414.17,1960) 1(3414.17,2040) 1(3414.17,2040) 1(3414.17,2060) 1(3414.17,2060) 1(3416.17,-69.79) 1(3416.17,-69.79) 1(3419.17,-74.79) 1(3419.17,-74.79) 1(3419.17,-72.79) 1(3419.17,-72.79) 1(3419.17,-66.79) 1(3419.17,-66.79) 1(3419.17,-64.79) 1(3419.17,-64.79) 1(3419.17,2315) 1(3419.17,2315) 1(3419.17,2335) 1(3419.17,2335) 1(3422.17,-69.79) 1(3422.17,-69.79) 1(3424.17,-69.79) 1(3424.17,-69.79) 1(3424.17,2325) 1(3424.17,2325) 1(3425.17,-75.79) 1(3425.17,-75.79) 1(3425.17,-63.79) 1(3425.17,-63.79) 1(3429.17,-79.79) 1(3429.17,-79.79) 1(3429.17,-59.79) 1(3429.17,-59.79) 1(3429.17,2320) 1(3429.17,2320) 1(3429.17,2330) 1(3429.17,2330) 1(3434.17,2325) 1(3434.17,2325) 1(3437.12,375) 1(3437.12,375) 1(3437.12,395) 1(3437.12,395) 1(3439.17,2315) 1(3439.17,2315) 1(3439.17,2335) 1(3439.17,2335) 1(3439.76,1495) 1(3439.76,1495) 1(3439.76,1515) 1(3439.76,1515) 1(3439.76,1800) 1(3439.76,1800) 1(3439.76,1820) 1(3439.76,1820) 1(3441.12,379) 1(3441.12,379) 1(3441.12,391) 1(3441.12,391) 1(3443.76,1499) 1(3443.76,1499) 1(3443.76,1511) 1(3443.76,1511) 1(3443.76,1804) 1(3443.76,1804) 1(3443.76,1816) 1(3443.76,1816) 1(3444.76,1505) 1(3444.76,1505) 1(3444.76,1810) 1(3444.76,1810) 1(3446.76,1505) 1(3446.76,1505) 1(3446.76,1810) 1(3446.76,1810) 1(3449.76,1500) 1(3449.76,1500) 1(3449.76,1502) 1(3449.76,1502) 1(3449.76,1508) 1(3449.76,1508) 1(3449.76,1510) 1(3449.76,1510) 1(3449.76,1805) 1(3449.76,1805) 1(3449.76,1807) 1(3449.76,1807) 1(3449.76,1813) 1(3449.76,1813) 1(3449.76,1815) 1(3449.76,1815) 1(3452.76,1505) 1(3452.76,1505) 1(3452.76,1810) 1(3452.76,1810) 1(3453.12,385) 1(3453.12,385) 1(3454.76,1505) 1(3454.76,1505) 1(3454.76,1810) 1(3454.76,1810) 1(3455.76,1499) 1(3455.76,1499) 1(3455.76,1511) 1(3455.76,1511) 1(3455.76,1804) 1(3455.76,1804) 1(3455.76,1816) 1(3455.76,1816) 1(3457.12,385) 1(3457.12,385) 1(3457.49,750) 1(3457.49,750) 1(3457.49,770) 1(3457.49,770) 1(3458.17,-123) 1(3458.17,-123) 1(3458.17,-103) 1(3458.17,-103) 1(3459.76,1495) 1(3459.76,1495) 1(3459.76,1515) 1(3459.76,1515) 1(3459.76,337.6) 1(3459.76,337.6) 1(3459.76,357.6) 1(3459.76,357.6) 1(3459.76,412.4) 1(3459.76,412.4) 1(3459.76,432.4) 1(3459.76,432.4) 1(3459.76,1800) 1(3459.76,1800) 1(3459.76,1820) 1(3459.76,1820) 1(3461.49,754) 1(3461.49,754) 1(3461.49,766) 1(3461.49,766) 1(3462.17,-119) 1(3462.17,-119) 1(3462.17,-107) 1(3462.17,-107) 1(3462.49,760) 1(3462.49,760) 1(3463.17,-113) 1(3463.17,-113) 1(3463.76,341.6) 1(3463.76,341.6) 1(3463.76,353.6) 1(3463.76,353.6) 1(3463.76,416.4) 1(3463.76,416.4) 1(3463.76,428.4) 1(3463.76,428.4) 1(3464.49,760) 1(3464.49,760) 1(3465.17,-113) 1(3465.17,-113) 1(3467.49,755) 1(3467.49,755) 1(3467.49,757) 1(3467.49,757) 1(3467.49,763) 1(3467.49,763) 1(3467.49,765) 1(3467.49,765) 1(3468.17,-118) 1(3468.17,-118) 1(3468.17,-116) 1(3468.17,-116) 1(3468.17,-110) 1(3468.17,-110) 1(3468.17,-108) 1(3468.17,-108) 1(3470.49,760) 1(3470.49,760) 1(3471.17,-113) 1(3471.17,-113) 1(3472.49,760) 1(3472.49,760) 1(3473.17,-113) 1(3473.17,-113) 1(3473.49,754) 1(3473.49,754) 1(3473.49,766) 1(3473.49,766) 1(3474.17,-119) 1(3474.17,-119) 1(3474.17,-107) 1(3474.17,-107) 1(3475.76,347.6) 1(3475.76,347.6) 1(3475.76,422.4) 1(3475.76,422.4) 1(3477.49,750) 1(3477.49,750) 1(3477.49,770) 1(3477.49,770) 1(3478.17,-123) 1(3478.17,-123) 1(3478.17,-103) 1(3478.17,-103) 1(3479.76,347.6) 1(3479.76,347.6) 1(3479.76,422.4) 1(3479.76,422.4) 1(3482.4,375) 1(3482.4,375) 1(3482.4,395) 1(3482.4,395) 1(3486.4,379) 1(3486.4,379) 1(3486.4,391) 1(3486.4,391) 1(3489.03,1118.74) 1(3489.03,1118.74) 1(3489.03,1138.74) 1(3489.03,1138.74) 1(3493.03,1122.74) 1(3493.03,1122.74) 1(3493.03,1134.74) 1(3493.03,1134.74) 1(3494.03,1128.74) 1(3494.03,1128.74) 1(3494.17,1940) 1(3494.17,1940) 1(3494.17,1960) 1(3494.17,1960) 1(3494.17,2040) 1(3494.17,2040) 1(3494.17,2060) 1(3494.17,2060) 1(3496.03,1128.74) 1(3496.03,1128.74) 1(3498.17,1944) 1(3498.17,1944) 1(3498.17,1956) 1(3498.17,1956) 1(3498.17,2044) 1(3498.17,2044) 1(3498.17,2056) 1(3498.17,2056) 1(3498.4,385) 1(3498.4,385) 1(3499.03,1123.74) 1(3499.03,1123.74) 1(3499.03,1125.74) 1(3499.03,1125.74) 1(3499.03,1131.74) 1(3499.03,1131.74) 1(3499.03,1133.74) 1(3499.03,1133.74) 1(3501.64,863.56) 1(3501.64,863.56) 1(3501.64,883.56) 1(3501.64,883.56) 1(3502.03,1128.74) 1(3502.03,1128.74) 1(3502.4,385) 1(3502.4,385) 1(3504.03,1128.74) 1(3504.03,1128.74) 1(3505.03,1122.74) 1(3505.03,1122.74) 1(3505.03,1134.74) 1(3505.03,1134.74) 1(3505.64,867.56) 1(3505.64,867.56) 1(3505.64,879.56) 1(3505.64,879.56) 1(3506.64,873.56) 1(3506.64,873.56) 1(3508.64,873.56) 1(3508.64,873.56) 1(3509.03,1118.74) 1(3509.03,1118.74) 1(3509.03,1138.74) 1(3509.03,1138.74) 1(3510.08,1673.5) 1(3510.08,1673.5) 1(3510.08,1693.5) 1(3510.08,1693.5) 1(3510.17,1944) 1(3510.17,1944) 1(3510.17,1956) 1(3510.17,1956) 1(3510.17,2044) 1(3510.17,2044) 1(3510.17,2056) 1(3510.17,2056) 1(3511.64,868.56) 1(3511.64,868.56) 1(3511.64,870.56) 1(3511.64,870.56) 1(3511.64,876.56) 1(3511.64,876.56) 1(3511.64,878.56) 1(3511.64,878.56) 1(3514.08,1677.5) 1(3514.08,1677.5) 1(3514.08,1689.5) 1(3514.08,1689.5) 1(3514.17,-79.79) 1(3514.17,-79.79) 1(3514.17,-59.79) 1(3514.17,-59.79) 1(3514.17,1940) 1(3514.17,1940) 1(3514.17,1960) 1(3514.17,1960) 1(3514.17,2040) 1(3514.17,2040) 1(3514.17,2060) 1(3514.17,2060) 1(3514.64,873.56) 1(3514.64,873.56) 1(3515.08,1683.5) 1(3515.08,1683.5) 1(3516.64,873.56) 1(3516.64,873.56) 1(3517.08,1683.5) 1(3517.08,1683.5) 1(3517.64,867.56) 1(3517.64,867.56) 1(3517.64,879.56) 1(3517.64,879.56) 1(3518.17,-75.79) 1(3518.17,-75.79) 1(3518.17,-63.79) 1(3518.17,-63.79) 1(3519.17,-69.79) 1(3519.17,-69.79) 1(3519.17,2315) 1(3519.17,2315) 1(3519.17,2335) 1(3519.17,2335) 1(3520.08,1678.5) 1(3520.08,1678.5) 1(3520.08,1680.5) 1(3520.08,1680.5) 1(3520.08,1686.5) 1(3520.08,1686.5) 1(3520.08,1688.5) 1(3520.08,1688.5) 1(3521.17,-69.79) 1(3521.17,-69.79) 1(3521.64,863.56) 1(3521.64,863.56) 1(3521.64,883.56) 1(3521.64,883.56) 1(3523.08,1683.5) 1(3523.08,1683.5) 1(3524.17,-74.79) 1(3524.17,-74.79) 1(3524.17,-72.79) 1(3524.17,-72.79) 1(3524.17,-66.79) 1(3524.17,-66.79) 1(3524.17,-64.79) 1(3524.17,-64.79) 1(3524.17,2325) 1(3524.17,2325) 1(3525.08,1683.5) 1(3525.08,1683.5) 1(3526.08,1677.5) 1(3526.08,1677.5) 1(3526.08,1689.5) 1(3526.08,1689.5) 1(3527.17,-69.79) 1(3527.17,-69.79) 1(3529.17,-69.79) 1(3529.17,-69.79) 1(3529.17,2320) 1(3529.17,2320) 1(3529.17,2330) 1(3529.17,2330) 1(3530.08,1673.5) 1(3530.08,1673.5) 1(3530.08,1693.5) 1(3530.08,1693.5) 1(3530.17,-75.79) 1(3530.17,-75.79) 1(3530.17,-63.79) 1(3530.17,-63.79) 1(3534.17,-79.79) 1(3534.17,-79.79) 1(3534.17,-59.79) 1(3534.17,-59.79) 1(3534.17,2325) 1(3534.17,2325) 1(3539.17,2315) 1(3539.17,2315) 1(3539.17,2335) 1(3539.17,2335) 1(3554.76,650) 1(3554.76,650) 1(3554.76,670) 1(3554.76,670) 1(3558.76,654) 1(3558.76,654) 1(3558.76,666) 1(3558.76,666) 1(3559.76,660) 1(3559.76,660) 1(3561.76,660) 1(3561.76,660) 1(3564.76,655) 1(3564.76,655) 1(3564.76,657) 1(3564.76,657) 1(3564.76,663) 1(3564.76,663) 1(3564.76,665) 1(3564.76,665) 1(3567.76,660) 1(3567.76,660) 1(3569.76,660) 1(3569.76,660) 1(3570.76,654) 1(3570.76,654) 1(3570.76,666) 1(3570.76,666) 1(3574.76,650) 1(3574.76,650) 1(3574.76,670) 1(3574.76,670) 1(3594.17,1940) 1(3594.17,1940) 1(3594.17,1960) 1(3594.17,1960) 1(3594.17,2040) 1(3594.17,2040) 1(3594.17,2060) 1(3594.17,2060) 1(3598.17,1944) 1(3598.17,1944) 1(3598.17,1956) 1(3598.17,1956) 1(3598.17,2044) 1(3598.17,2044) 1(3598.17,2056) 1(3598.17,2056) 1(3608.58,477.72) 1(3608.58,477.72) 1(3608.58,497.72) 1(3608.58,497.72) 1(3610.17,1944) 1(3610.17,1944) 1(3610.17,1956) 1(3610.17,1956) 1(3610.17,2044) 1(3610.17,2044) 1(3610.17,2056) 1(3610.17,2056) 1(3612.58,481.72) 1(3612.58,481.72) 1(3612.58,493.72) 1(3612.58,493.72) 1(3613.58,487.72) 1(3613.58,487.72) 1(3614.17,1940) 1(3614.17,1940) 1(3614.17,1960) 1(3614.17,1960) 1(3614.17,2040) 1(3614.17,2040) 1(3614.17,2060) 1(3614.17,2060) 1(3615.58,487.72) 1(3615.58,487.72) 1(3618.58,482.72) 1(3618.58,482.72) 1(3618.58,484.72) 1(3618.58,484.72) 1(3618.58,490.72) 1(3618.58,490.72) 1(3618.58,492.72) 1(3618.58,492.72) 1(3619.17,2315) 1(3619.17,2315) 1(3619.17,2335) 1(3619.17,2335) 1(3621.58,487.72) 1(3621.58,487.72) 1(3623.58,487.72) 1(3623.58,487.72) 1(3624.17,2325) 1(3624.17,2325) 1(3624.58,481.72) 1(3624.58,481.72) 1(3624.58,493.72) 1(3624.58,493.72) 1(3628.58,477.72) 1(3628.58,477.72) 1(3628.58,497.72) 1(3628.58,497.72) 1(3629.17,2320) 1(3629.17,2320) 1(3629.17,2330) 1(3629.17,2330) 1(3634.17,2325) 1(3634.17,2325) 1(3639.17,2315) 1(3639.17,2315) 1(3639.17,2335) 1(3639.17,2335) 1(3670.75,-99.16) 1(3670.75,-79.16) 1(3694.17,1940) 1(3694.17,1940) 1(3694.17,1960) 1(3694.17,1960) 1(3694.17,2040) 1(3694.17,2040) 1(3694.17,2060) 1(3694.17,2060) 1(3698.17,1944) 1(3698.17,1944) 1(3698.17,1956) 1(3698.17,1956) 1(3698.17,2044) 1(3698.17,2044) 1(3698.17,2056) 1(3698.17,2056) 1(3710.17,1944) 1(3710.17,1944) 1(3710.17,1956) 1(3710.17,1956) 1(3710.17,2044) 1(3710.17,2044) 1(3710.17,2056) 1(3710.17,2056) 1(3714.17,1940) 1(3714.17,1940) 1(3714.17,1960) 1(3714.17,1960) 1(3714.17,2040) 1(3714.17,2040) 1(3714.17,2060) 1(3714.17,2060) 1(3764.17,1527.19) 1(3764.17,1531.19) 1(3764.17,1543.19) 1(3764.17,1547.19) 1(3769.17,1805) 1(3769.17,1805) 1(3769.17,1810) 1(3769.17,1810) 1(3769.17,1820) 1(3769.17,1820) 1(3769.17,1825) 1(3769.17,1825) 1(3773.17,1809) 1(3773.17,1809) 1(3773.17,1812) 1(3773.17,1812) 1(3773.17,1818) 1(3773.17,1818) 1(3773.17,1821) 1(3773.17,1821) 1(3774.17,1759.09) 1(3774.17,1763.09) 1(3774.17,1775.09) 1(3774.17,1779.09) 1(3774.17,1805) 1(3774.17,1805) 1(3774.17,1815) 1(3774.17,1815) 1(3774.17,1825) 1(3774.17,1825) 1(3776.17,1809) 1(3776.17,1809) 1(3776.17,1815) 1(3776.17,1815) 1(3776.17,1821) 1(3776.17,1821) 1(3779.17,1810) 1(3779.17,1810) 1(3779.17,1812) 1(3779.17,1812) 1(3779.17,1818) 1(3779.17,1818) 1(3779.17,1820) 1(3779.17,1820) 1(3782.17,1809) 1(3782.17,1809) 1(3782.17,1815) 1(3782.17,1815) 1(3782.17,1821) 1(3782.17,1821) 1(3784.17,1805) 1(3784.17,1805) 1(3784.17,1815) 1(3784.17,1815) 1(3784.17,1825) 1(3784.17,1825) 1(3785.17,1809) 1(3785.17,1809) 1(3785.17,1812) 1(3785.17,1812) 1(3785.17,1818) 1(3785.17,1818) 1(3785.17,1821) 1(3785.17,1821) 1(3789.17,1805) 1(3789.17,1805) 1(3789.17,1810) 1(3789.17,1810) 1(3789.17,1820) 1(3789.17,1820) 1(3789.17,1825) 1(3789.17,1825) 1(3794.17,1940) 1(3794.17,1940) 1(3794.17,1960) 1(3794.17,1960) 1(3794.17,2040) 1(3794.17,2040) 1(3794.17,2060) 1(3794.17,2060) 1(3798.17,1944) 1(3798.17,1944) 1(3798.17,1956) 1(3798.17,1956) 1(3798.17,2044) 1(3798.17,2044) 1(3798.17,2056) 1(3798.17,2056) 1(3810.17,1944) 1(3810.17,1944) 1(3810.17,1956) 1(3810.17,1956) 1(3810.17,2044) 1(3810.17,2044) 1(3810.17,2056) 1(3810.17,2056) 1(3814.17,1940) 1(3814.17,1940) 1(3814.17,1960) 1(3814.17,1960) 1(3814.17,2040) 1(3814.17,2040) 1(3814.17,2060) 1(3814.17,2060) 1(3854.17,1552.19) 1(3854.17,1556.19) 1(3854.17,1568.19) 1(3854.17,1572.19) 1(3867.6,-99.16) 1(3867.6,-79.16) 1(4016.36,2195) 1(4016.36,2195) 1(4016.36,2215) 1(4016.36,2215) 1(4020.36,2199) 1(4020.36,2199) 1(4020.36,2211) 1(4020.36,2211) 1(4021.36,2205) 1(4021.36,2205) 1(4023.36,2205) 1(4023.36,2205) 1(4024.17,1494.22) 1(4024.17,1494.22) 1(4024.17,1499.22) 1(4024.17,1499.22) 1(4024.17,1509.22) 1(4024.17,1509.22) 1(4024.17,1514.22) 1(4024.17,1514.22) 1(4024.17,1800) 1(4024.17,1800) 1(4024.17,1805) 1(4024.17,1805) 1(4024.17,1815) 1(4024.17,1815) 1(4024.17,1820) 1(4024.17,1820) 1(4026.36,2200) 1(4026.36,2200) 1(4026.36,2202) 1(4026.36,2202) 1(4026.36,2208) 1(4026.36,2208) 1(4026.36,2210) 1(4026.36,2210) 1(4028.17,1498.22) 1(4028.17,1498.22) 1(4028.17,1501.22) 1(4028.17,1501.22) 1(4028.17,1507.22) 1(4028.17,1507.22) 1(4028.17,1510.22) 1(4028.17,1510.22) 1(4028.17,1804) 1(4028.17,1804) 1(4028.17,1807) 1(4028.17,1807) 1(4028.17,1813) 1(4028.17,1813) 1(4028.17,1816) 1(4028.17,1816) 1(4029.17,1494.22) 1(4029.17,1494.22) 1(4029.17,1504.22) 1(4029.17,1504.22) 1(4029.17,1514.22) 1(4029.17,1514.22) 1(4029.17,1800) 1(4029.17,1800) 1(4029.17,1810) 1(4029.17,1810) 1(4029.17,1820) 1(4029.17,1820) 1(4029.36,2205) 1(4029.36,2205) 1(4031.17,1498.22) 1(4031.17,1498.22) 1(4031.17,1504.22) 1(4031.17,1504.22) 1(4031.17,1510.22) 1(4031.17,1510.22) 1(4031.17,1804) 1(4031.17,1804) 1(4031.17,1810) 1(4031.17,1810) 1(4031.17,1816) 1(4031.17,1816) 1(4031.36,2205) 1(4031.36,2205) 1(4032.36,2199) 1(4032.36,2199) 1(4032.36,2211) 1(4032.36,2211) 1(4034.17,1499.22) 1(4034.17,1499.22) 1(4034.17,1501.22) 1(4034.17,1501.22) 1(4034.17,1507.22) 1(4034.17,1507.22) 1(4034.17,1509.22) 1(4034.17,1509.22) 1(4034.17,1805) 1(4034.17,1805) 1(4034.17,1807) 1(4034.17,1807) 1(4034.17,1813) 1(4034.17,1813) 1(4034.17,1815) 1(4034.17,1815) 1(4036.36,2195) 1(4036.36,2195) 1(4036.36,2215) 1(4036.36,2215) 1(4037.17,1498.22) 1(4037.17,1498.22) 1(4037.17,1504.22) 1(4037.17,1504.22) 1(4037.17,1510.22) 1(4037.17,1510.22) 1(4037.17,1804) 1(4037.17,1804) 1(4037.17,1810) 1(4037.17,1810) 1(4037.17,1816) 1(4037.17,1816) 1(4039.17,1494.22) 1(4039.17,1494.22) 1(4039.17,1504.22) 1(4039.17,1504.22) 1(4039.17,1514.22) 1(4039.17,1514.22) 1(4039.17,1800) 1(4039.17,1800) 1(4039.17,1810) 1(4039.17,1810) 1(4039.17,1820) 1(4039.17,1820) 1(4040.17,1498.22) 1(4040.17,1498.22) 1(4040.17,1501.22) 1(4040.17,1501.22) 1(4040.17,1507.22) 1(4040.17,1507.22) 1(4040.17,1510.22) 1(4040.17,1510.22) 1(4040.17,1804) 1(4040.17,1804) 1(4040.17,1807) 1(4040.17,1807) 1(4040.17,1813) 1(4040.17,1813) 1(4040.17,1816) 1(4040.17,1816) 1(4044.17,1494.22) 1(4044.17,1494.22) 1(4044.17,1499.22) 1(4044.17,1499.22) 1(4044.17,1509.22) 1(4044.17,1509.22) 1(4044.17,1514.22) 1(4044.17,1514.22) 1(4044.17,1800) 1(4044.17,1800) 1(4044.17,1805) 1(4044.17,1805) 1(4044.17,1815) 1(4044.17,1815) 1(4044.17,1820) 1(4044.17,1820) 1(4051.46,1040) 1(4051.46,1040) 1(4051.46,1060) 1(4051.46,1060) 1(4051.46,1140) 1(4051.46,1140) 1(4051.46,1160) 1(4051.46,1160) 1(4051.46,1240) 1(4051.46,1240) 1(4051.46,1260) 1(4051.46,1260) 1(4056.46,1050) 1(4056.46,1050) 1(4056.46,1150) 1(4056.46,1150) 1(4056.46,1250) 1(4056.46,1250) 1(4061.46,1045) 1(4061.46,1045) 1(4061.46,1055) 1(4061.46,1055) 1(4061.46,1145) 1(4061.46,1145) 1(4061.46,1155) 1(4061.46,1155) 1(4061.46,1245) 1(4061.46,1245) 1(4061.46,1255) 1(4061.46,1255) 1(4064.17,-60) 1(4064.17,-60) 1(4064.17,-40) 1(4064.17,-40) 1(4066.46,1050) 1(4066.46,1050) 1(4066.46,1150) 1(4066.46,1150) 1(4066.46,1250) 1(4066.46,1250) 1(4069.17,-50) 1(4069.17,-50) 1(4071.46,1040) 1(4071.46,1040) 1(4071.46,1060) 1(4071.46,1060) 1(4071.46,1140) 1(4071.46,1140) 1(4071.46,1160) 1(4071.46,1160) 1(4071.46,1240) 1(4071.46,1240) 1(4071.46,1260) 1(4071.46,1260) 1(4074.17,-55) 1(4074.17,-55) 1(4074.17,-45) 1(4074.17,-45) 1(4079.17,-50) 1(4079.17,-50) 1(4084.17,-60) 1(4084.17,-60) 1(4084.17,-40) 1(4084.17,-40) 1(4094.17,240) 1(4094.17,240) 1(4094.17,260) 1(4094.17,260) 1(4094.17,340) 1(4094.17,340) 1(4094.17,360) 1(4094.17,360) 1(4094.17,1755) 1(4094.17,1755) 1(4094.17,1760) 1(4094.17,1760) 1(4094.17,1770) 1(4094.17,1770) 1(4094.17,1775) 1(4094.17,1775) 1(4094.17,1940) 1(4094.17,1940) 1(4094.17,1960) 1(4094.17,1960) 1(4094.17,2040) 1(4094.17,2040) 1(4094.17,2060) 1(4094.17,2060) 1(4098.17,244) 1(4098.17,244) 1(4098.17,256) 1(4098.17,256) 1(4098.17,344) 1(4098.17,344) 1(4098.17,356) 1(4098.17,356) 1(4098.17,1759) 1(4098.17,1759) 1(4098.17,1762) 1(4098.17,1762) 1(4098.17,1768) 1(4098.17,1768) 1(4098.17,1771) 1(4098.17,1771) 1(4098.17,1944) 1(4098.17,1944) 1(4098.17,1956) 1(4098.17,1956) 1(4098.17,2044) 1(4098.17,2044) 1(4098.17,2056) 1(4098.17,2056) 1(4099.17,1755) 1(4099.17,1755) 1(4099.17,1765) 1(4099.17,1765) 1(4099.17,1775) 1(4099.17,1775) 1(4101.17,1759) 1(4101.17,1759) 1(4101.17,1765) 1(4101.17,1765) 1(4101.17,1771) 1(4101.17,1771) 1(4104.17,1760) 1(4104.17,1760) 1(4104.17,1762) 1(4104.17,1762) 1(4104.17,1768) 1(4104.17,1768) 1(4104.17,1770) 1(4104.17,1770) 1(4107.17,1759) 1(4107.17,1759) 1(4107.17,1765) 1(4107.17,1765) 1(4107.17,1771) 1(4107.17,1771) 1(4109.17,1755) 1(4109.17,1755) 1(4109.17,1765) 1(4109.17,1765) 1(4109.17,1775) 1(4109.17,1775) 1(4110.17,244) 1(4110.17,244) 1(4110.17,256) 1(4110.17,256) 1(4110.17,344) 1(4110.17,344) 1(4110.17,356) 1(4110.17,356) 1(4110.17,1759) 1(4110.17,1759) 1(4110.17,1762) 1(4110.17,1762) 1(4110.17,1768) 1(4110.17,1768) 1(4110.17,1771) 1(4110.17,1771) 1(4110.17,1944) 1(4110.17,1944) 1(4110.17,1956) 1(4110.17,1956) 1(4110.17,2044) 1(4110.17,2044) 1(4110.17,2056) 1(4110.17,2056) 1(4114.17,240) 1(4114.17,240) 1(4114.17,260) 1(4114.17,260) 1(4114.17,340) 1(4114.17,340) 1(4114.17,360) 1(4114.17,360) 1(4114.17,1755) 1(4114.17,1755) 1(4114.17,1760) 1(4114.17,1760) 1(4114.17,1770) 1(4114.17,1770) 1(4114.17,1775) 1(4114.17,1775) 1(4114.17,1940) 1(4114.17,1940) 1(4114.17,1960) 1(4114.17,1960) 1(4114.17,2040) 1(4114.17,2040) 1(4114.17,2060) 1(4114.17,2060) 1(4164.17,-60) 1(4164.17,-60) 1(4164.17,-40) 1(4164.17,-40) 1(4169.17,-50) 1(4169.17,-50) 1(4169.17,475) 1(4169.17,475) 1(4169.17,495) 1(4169.17,495) 1(4169.17,1805) 1(4169.17,1805) 1(4169.17,1825) 1(4169.17,1825) 1(4173.17,479) 1(4173.17,479) 1(4173.17,491) 1(4173.17,491) 1(4173.17,1809) 1(4173.17,1809) 1(4173.17,1821) 1(4173.17,1821) 1(4174.17,-55) 1(4174.17,-55) 1(4174.17,-45) 1(4174.17,-45) 1(4174.17,485) 1(4174.17,485) 1(4174.17,1815) 1(4174.17,1815) 1(4176.17,485) 1(4176.17,485) 1(4176.17,1815) 1(4176.17,1815) 1(4179.17,-50) 1(4179.17,-50) 1(4179.17,480) 1(4179.17,480) 1(4179.17,482) 1(4179.17,482) 1(4179.17,488) 1(4179.17,488) 1(4179.17,490) 1(4179.17,490) 1(4179.17,1810) 1(4179.17,1810) 1(4179.17,1812) 1(4179.17,1812) 1(4179.17,1818) 1(4179.17,1818) 1(4179.17,1820) 1(4179.17,1820) 1(4182.17,485) 1(4182.17,485) 1(4182.17,1815) 1(4182.17,1815) 1(4184.17,-60) 1(4184.17,-60) 1(4184.17,-40) 1(4184.17,-40) 1(4184.17,485) 1(4184.17,485) 1(4184.17,1815) 1(4184.17,1815) 1(4185.17,479) 1(4185.17,479) 1(4185.17,491) 1(4185.17,491) 1(4185.17,1809) 1(4185.17,1809) 1(4185.17,1821) 1(4185.17,1821) 1(4189.17,475) 1(4189.17,475) 1(4189.17,495) 1(4189.17,495) 1(4189.17,1805) 1(4189.17,1805) 1(4189.17,1825) 1(4189.17,1825) 1(4194.17,240) 1(4194.17,240) 1(4194.17,260) 1(4194.17,260) 1(4194.17,340) 1(4194.17,340) 1(4194.17,360) 1(4194.17,360) 1(4194.17,1940) 1(4194.17,1940) 1(4194.17,1960) 1(4194.17,1960) 1(4194.17,2040) 1(4194.17,2040) 1(4194.17,2060) 1(4194.17,2060) 1(4198.17,244) 1(4198.17,244) 1(4198.17,256) 1(4198.17,256) 1(4198.17,344) 1(4198.17,344) 1(4198.17,356) 1(4198.17,356) 1(4198.17,1944) 1(4198.17,1944) 1(4198.17,1956) 1(4198.17,1956) 1(4198.17,2044) 1(4198.17,2044) 1(4198.17,2056) 1(4198.17,2056) 1(4204.17,620) 1(4204.17,620) 1(4204.17,720) 1(4204.17,720) 1(4204.17,820) 1(4204.17,820) 1(4204.17,920) 1(4204.17,920) 1(4204.17,1020) 1(4204.17,1020) 1(4204.17,1280) 1(4204.17,1280) 1(4204.17,1380) 1(4204.17,1380) 1(4204.17,1480) 1(4204.17,1480) 1(4204.17,1580) 1(4204.17,1580) 1(4204.17,1680) 1(4204.17,1680) 1(4208.17,620) 1(4208.17,620) 1(4208.17,720) 1(4208.17,720) 1(4208.17,820) 1(4208.17,820) 1(4208.17,920) 1(4208.17,920) 1(4208.17,1020) 1(4208.17,1020) 1(4208.17,1280) 1(4208.17,1280) 1(4208.17,1380) 1(4208.17,1380) 1(4208.17,1480) 1(4208.17,1480) 1(4208.17,1580) 1(4208.17,1580) 1(4208.17,1680) 1(4208.17,1680) 1(4209.17,610) 1(4209.17,610) 1(4209.17,615) 1(4209.17,615) 1(4209.17,625) 1(4209.17,625) 1(4209.17,630) 1(4209.17,630) 1(4209.17,710) 1(4209.17,710) 1(4209.17,715) 1(4209.17,715) 1(4209.17,725) 1(4209.17,725) 1(4209.17,730) 1(4209.17,730) 1(4209.17,810) 1(4209.17,810) 1(4209.17,815) 1(4209.17,815) 1(4209.17,825) 1(4209.17,825) 1(4209.17,830) 1(4209.17,830) 1(4209.17,910) 1(4209.17,910) 1(4209.17,915) 1(4209.17,915) 1(4209.17,925) 1(4209.17,925) 1(4209.17,930) 1(4209.17,930) 1(4209.17,1010) 1(4209.17,1010) 1(4209.17,1015) 1(4209.17,1015) 1(4209.17,1025) 1(4209.17,1025) 1(4209.17,1030) 1(4209.17,1030) 1(4209.17,1270) 1(4209.17,1270) 1(4209.17,1275) 1(4209.17,1275) 1(4209.17,1285) 1(4209.17,1285) 1(4209.17,1290) 1(4209.17,1290) 1(4209.17,1370) 1(4209.17,1370) 1(4209.17,1375) 1(4209.17,1375) 1(4209.17,1385) 1(4209.17,1385) 1(4209.17,1390) 1(4209.17,1390) 1(4209.17,1470) 1(4209.17,1470) 1(4209.17,1475) 1(4209.17,1475) 1(4209.17,1485) 1(4209.17,1485) 1(4209.17,1490) 1(4209.17,1490) 1(4209.17,1570) 1(4209.17,1570) 1(4209.17,1575) 1(4209.17,1575) 1(4209.17,1585) 1(4209.17,1585) 1(4209.17,1590) 1(4209.17,1590) 1(4209.17,1670) 1(4209.17,1670) 1(4209.17,1675) 1(4209.17,1675) 1(4209.17,1685) 1(4209.17,1685) 1(4209.17,1690) 1(4209.17,1690) 1(4210.17,244) 1(4210.17,244) 1(4210.17,256) 1(4210.17,256) 1(4210.17,344) 1(4210.17,344) 1(4210.17,356) 1(4210.17,356) 1(4210.17,1944) 1(4210.17,1944) 1(4210.17,1956) 1(4210.17,1956) 1(4210.17,2044) 1(4210.17,2044) 1(4210.17,2056) 1(4210.17,2056) 1(4211.17,614) 1(4211.17,614) 1(4211.17,617) 1(4211.17,617) 1(4211.17,623) 1(4211.17,623) 1(4211.17,626) 1(4211.17,626) 1(4211.17,714) 1(4211.17,714) 1(4211.17,717) 1(4211.17,717) 1(4211.17,723) 1(4211.17,723) 1(4211.17,726) 1(4211.17,726) 1(4211.17,814) 1(4211.17,814) 1(4211.17,817) 1(4211.17,817) 1(4211.17,823) 1(4211.17,823) 1(4211.17,826) 1(4211.17,826) 1(4211.17,914) 1(4211.17,914) 1(4211.17,917) 1(4211.17,917) 1(4211.17,923) 1(4211.17,923) 1(4211.17,926) 1(4211.17,926) 1(4211.17,1014) 1(4211.17,1014) 1(4211.17,1017) 1(4211.17,1017) 1(4211.17,1023) 1(4211.17,1023) 1(4211.17,1026) 1(4211.17,1026) 1(4211.17,1274) 1(4211.17,1274) 1(4211.17,1277) 1(4211.17,1277) 1(4211.17,1283) 1(4211.17,1283) 1(4211.17,1286) 1(4211.17,1286) 1(4211.17,1374) 1(4211.17,1374) 1(4211.17,1377) 1(4211.17,1377) 1(4211.17,1383) 1(4211.17,1383) 1(4211.17,1386) 1(4211.17,1386) 1(4211.17,1474) 1(4211.17,1474) 1(4211.17,1477) 1(4211.17,1477) 1(4211.17,1483) 1(4211.17,1483) 1(4211.17,1486) 1(4211.17,1486) 1(4211.17,1574) 1(4211.17,1574) 1(4211.17,1577) 1(4211.17,1577) 1(4211.17,1583) 1(4211.17,1583) 1(4211.17,1586) 1(4211.17,1586) 1(4211.17,1674) 1(4211.17,1674) 1(4211.17,1677) 1(4211.17,1677) 1(4211.17,1683) 1(4211.17,1683) 1(4211.17,1686) 1(4211.17,1686) 1(4214.17,240) 1(4214.17,240) 1(4214.17,260) 1(4214.17,260) 1(4214.17,340) 1(4214.17,340) 1(4214.17,360) 1(4214.17,360) 1(4214.17,615) 1(4214.17,615) 1(4214.17,617) 1(4214.17,617) 1(4214.17,623) 1(4214.17,623) 1(4214.17,625) 1(4214.17,625) 1(4214.17,715) 1(4214.17,715) 1(4214.17,717) 1(4214.17,717) 1(4214.17,723) 1(4214.17,723) 1(4214.17,725) 1(4214.17,725) 1(4214.17,815) 1(4214.17,815) 1(4214.17,817) 1(4214.17,817) 1(4214.17,823) 1(4214.17,823) 1(4214.17,825) 1(4214.17,825) 1(4214.17,915) 1(4214.17,915) 1(4214.17,917) 1(4214.17,917) 1(4214.17,923) 1(4214.17,923) 1(4214.17,925) 1(4214.17,925) 1(4214.17,1015) 1(4214.17,1015) 1(4214.17,1017) 1(4214.17,1017) 1(4214.17,1023) 1(4214.17,1023) 1(4214.17,1025) 1(4214.17,1025) 1(4214.17,1275) 1(4214.17,1275) 1(4214.17,1277) 1(4214.17,1277) 1(4214.17,1283) 1(4214.17,1283) 1(4214.17,1285) 1(4214.17,1285) 1(4214.17,1375) 1(4214.17,1375) 1(4214.17,1377) 1(4214.17,1377) 1(4214.17,1383) 1(4214.17,1383) 1(4214.17,1385) 1(4214.17,1385) 1(4214.17,1475) 1(4214.17,1475) 1(4214.17,1477) 1(4214.17,1477) 1(4214.17,1483) 1(4214.17,1483) 1(4214.17,1485) 1(4214.17,1485) 1(4214.17,1575) 1(4214.17,1575) 1(4214.17,1577) 1(4214.17,1577) 1(4214.17,1583) 1(4214.17,1583) 1(4214.17,1585) 1(4214.17,1585) 1(4214.17,1675) 1(4214.17,1675) 1(4214.17,1677) 1(4214.17,1677) 1(4214.17,1683) 1(4214.17,1683) 1(4214.17,1685) 1(4214.17,1685) 1(4214.17,1940) 1(4214.17,1940) 1(4214.17,1960) 1(4214.17,1960) 1(4214.17,2040) 1(4214.17,2040) 1(4214.17,2060) 1(4214.17,2060) 1(4217.17,614) 1(4217.17,614) 1(4217.17,617) 1(4217.17,617) 1(4217.17,623) 1(4217.17,623) 1(4217.17,626) 1(4217.17,626) 1(4217.17,714) 1(4217.17,714) 1(4217.17,717) 1(4217.17,717) 1(4217.17,723) 1(4217.17,723) 1(4217.17,726) 1(4217.17,726) 1(4217.17,814) 1(4217.17,814) 1(4217.17,817) 1(4217.17,817) 1(4217.17,823) 1(4217.17,823) 1(4217.17,826) 1(4217.17,826) 1(4217.17,914) 1(4217.17,914) 1(4217.17,917) 1(4217.17,917) 1(4217.17,923) 1(4217.17,923) 1(4217.17,926) 1(4217.17,926) 1(4217.17,1014) 1(4217.17,1014) 1(4217.17,1017) 1(4217.17,1017) 1(4217.17,1023) 1(4217.17,1023) 1(4217.17,1026) 1(4217.17,1026) 1(4217.17,1274) 1(4217.17,1274) 1(4217.17,1277) 1(4217.17,1277) 1(4217.17,1283) 1(4217.17,1283) 1(4217.17,1286) 1(4217.17,1286) 1(4217.17,1374) 1(4217.17,1374) 1(4217.17,1377) 1(4217.17,1377) 1(4217.17,1383) 1(4217.17,1383) 1(4217.17,1386) 1(4217.17,1386) 1(4217.17,1474) 1(4217.17,1474) 1(4217.17,1477) 1(4217.17,1477) 1(4217.17,1483) 1(4217.17,1483) 1(4217.17,1486) 1(4217.17,1486) 1(4217.17,1574) 1(4217.17,1574) 1(4217.17,1577) 1(4217.17,1577) 1(4217.17,1583) 1(4217.17,1583) 1(4217.17,1586) 1(4217.17,1586) 1(4217.17,1674) 1(4217.17,1674) 1(4217.17,1677) 1(4217.17,1677) 1(4217.17,1683) 1(4217.17,1683) 1(4217.17,1686) 1(4217.17,1686) 1(4219.17,610) 1(4219.17,610) 1(4219.17,615) 1(4219.17,615) 1(4219.17,625) 1(4219.17,625) 1(4219.17,630) 1(4219.17,630) 1(4219.17,710) 1(4219.17,710) 1(4219.17,715) 1(4219.17,715) 1(4219.17,725) 1(4219.17,725) 1(4219.17,730) 1(4219.17,730) 1(4219.17,810) 1(4219.17,810) 1(4219.17,815) 1(4219.17,815) 1(4219.17,825) 1(4219.17,825) 1(4219.17,830) 1(4219.17,830) 1(4219.17,910) 1(4219.17,910) 1(4219.17,915) 1(4219.17,915) 1(4219.17,925) 1(4219.17,925) 1(4219.17,930) 1(4219.17,930) 1(4219.17,1010) 1(4219.17,1010) 1(4219.17,1015) 1(4219.17,1015) 1(4219.17,1025) 1(4219.17,1025) 1(4219.17,1030) 1(4219.17,1030) 1(4219.17,1270) 1(4219.17,1270) 1(4219.17,1275) 1(4219.17,1275) 1(4219.17,1285) 1(4219.17,1285) 1(4219.17,1290) 1(4219.17,1290) 1(4219.17,1370) 1(4219.17,1370) 1(4219.17,1375) 1(4219.17,1375) 1(4219.17,1385) 1(4219.17,1385) 1(4219.17,1390) 1(4219.17,1390) 1(4219.17,1470) 1(4219.17,1470) 1(4219.17,1475) 1(4219.17,1475) 1(4219.17,1485) 1(4219.17,1485)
